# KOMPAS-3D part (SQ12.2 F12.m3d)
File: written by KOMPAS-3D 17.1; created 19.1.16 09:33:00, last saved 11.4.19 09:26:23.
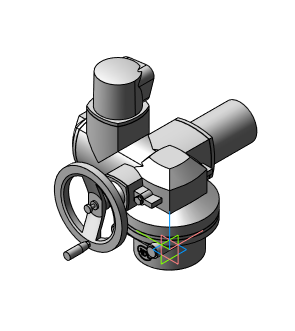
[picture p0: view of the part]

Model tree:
1. Операция без истории:2  (labels: Сталь 20  ГОСТ 1050-88)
